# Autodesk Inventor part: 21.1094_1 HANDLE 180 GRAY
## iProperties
Created: 2007-03
Part Number: 21.1094_1 HANDLE 180 GRAY
Document SubType Name: Modeling
Designer: Andy Moles
Material: ABS Plastic
Density: 1.06 g/cm^3
Mass: 58.2926 g
Surface Area: 202.508 cm^2
Volume: 54.993 cm^3
Author: Andy Moles
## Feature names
1. Extrusion1
2. Extrusion2
3. Extrusion3
4. Extrusion4
5. Fillet1
6. Fillet2
7. Fillet3
